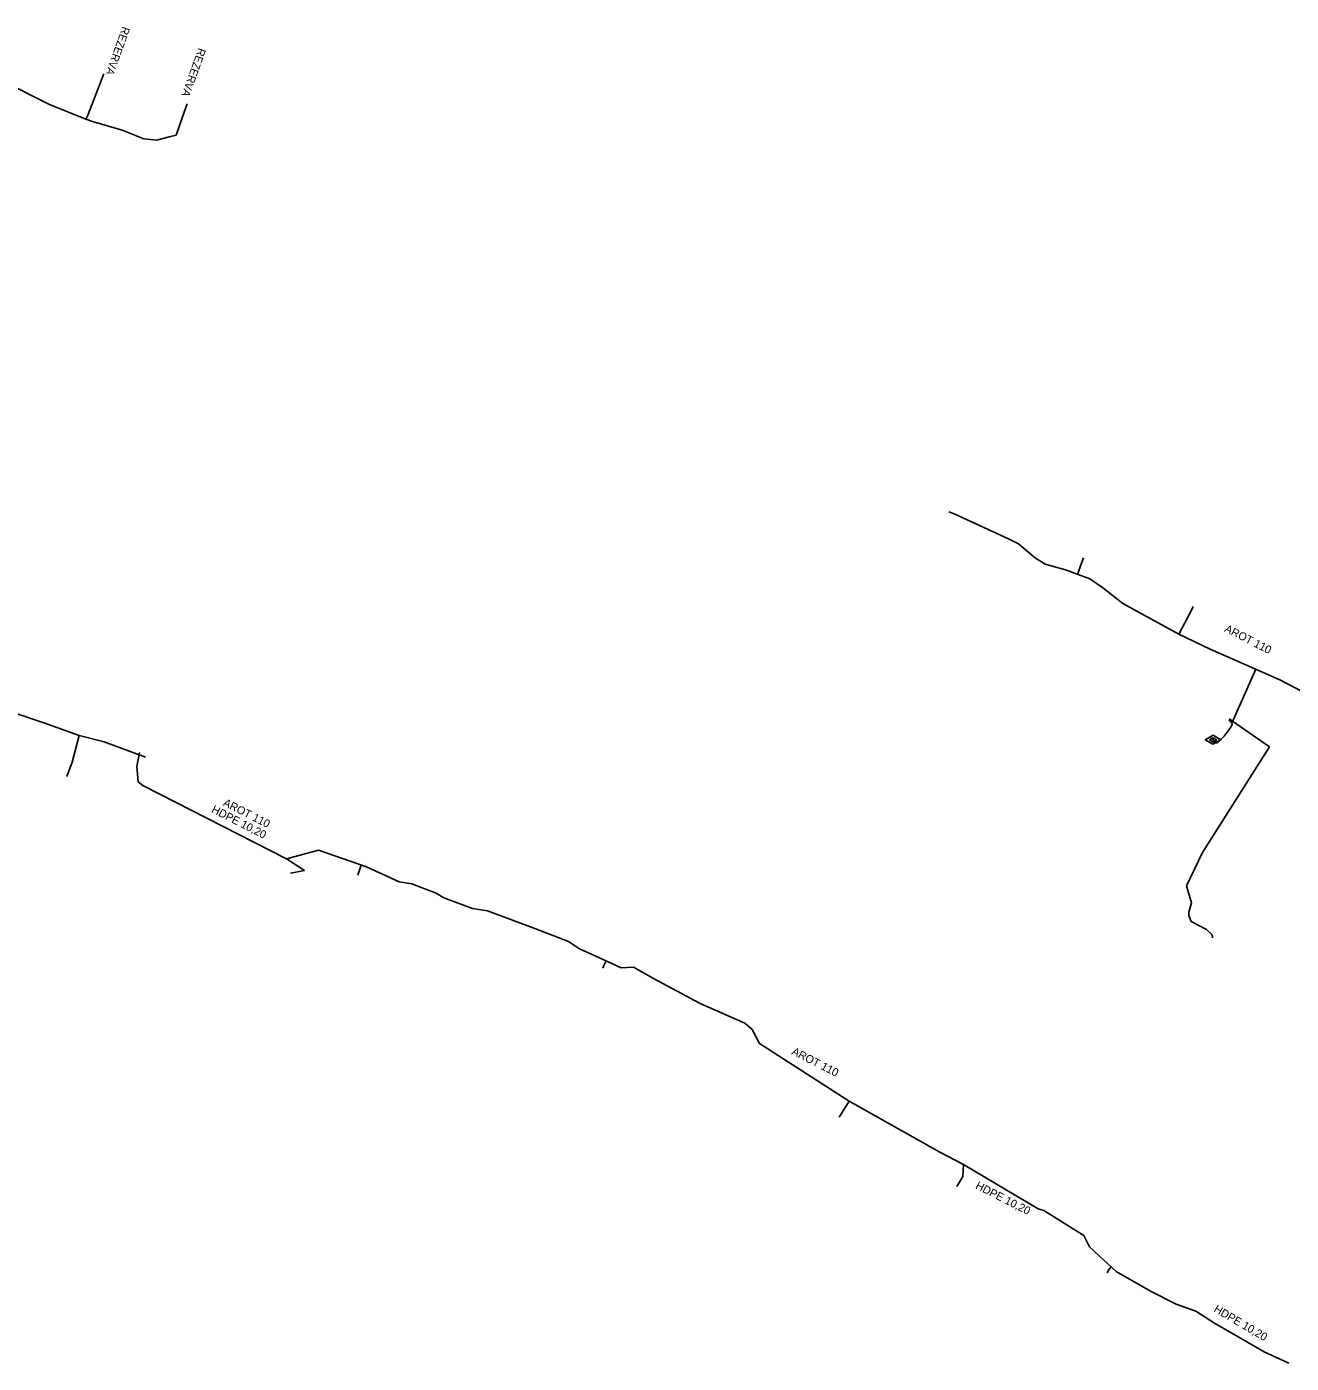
# Model space of a CAD drawing. Extents: x -651943 to -618711, y -1138561 to -1100552.
# Drawn here: x -644703.5 to -644585, y -1119211.8 to -1119086.6 of the extents above; entities that cross this region are included whole.
import ezdxf

# ---------------------------------------------------------------- set-up
doc = ezdxf.new("R2010")
doc.units = 0
doc.layers.add('KT trasa', color=7, linetype='Continuous')
doc.layers.add('KT zařízení', color=7, linetype='Continuous')

# ---------------------------------------------------------------- blocks, each defined once
blk = doc.blocks.new('TVSPO_1')
at = {"layer": 'KT zařízení'}
for p, q in [((-0.074, 0.002), (0, 0.044)), ((-0.001, -0.041), (-0.074, 0.002)), ((-0.035, 0), (0, 0.02)), ((0.073, 0.001), (-0.001, -0.041)), ((0, 0.044), (0.073, 0.001)), ((0, 0.02), (0.035, 0)), ((0.035, 0), (0, -0.02)), ((0, -0.02), (-0.035, 0))]:
    blk.add_line(p, q, dxfattribs=at)

msp = doc.modelspace()

# ---------------------------------------------------------------- linework, layer by layer
at = {"layer": 'KT trasa'}
for p, q in [((-644706.01, -1119091.49), (-644701.34, -1119093.83)), ((-644697.74, -1119094.84), (-644696.45, -1119091.53)), ((-644696.24, -1119090.96), (-644696.45, -1119091.53)), ((-644701.34, -1119093.83), (-644697.93, -1119095.23)), ((-644688.43, -1119093.77), (-644688.71, -1119094.56)), ((-644697.93, -1119095.23), (-644697.74, -1119094.84)), ((-644697.93, -1119095.23), (-644697.31, -1119095.42)), ((-644689.45, -1119096.73), (-644688.71, -1119094.56)), ((-644697.31, -1119095.42), (-644694.52, -1119096.26)), ((-644694.52, -1119096.26), (-644692.5, -1119097.07)), ((-644692.5, -1119097.07), (-644691.27, -1119097.17)), ((-644691.27, -1119097.17), (-644690.13, -1119096.87)), ((-644690.13, -1119096.87), (-644689.45, -1119096.73)), ((-644616.56, -1119132.22), (-644617.06, -1119132.01)), ((-644611.47, -1119134.54), (-644616.56, -1119132.22)), ((-644610.53, -1119135.01), (-644611.47, -1119134.54)), ((-644608.93, -1119136.35), (-644610.53, -1119135.01)), ((-644608.03, -1119136.93), (-644608.93, -1119136.35)), ((-644604.42, -1119136.34), (-644604.59, -1119136.75)), ((-644606.13, -1119137.47), (-644608.03, -1119136.93)), ((-644603.83, -1119138.3), (-644606.13, -1119137.47)), ((-644605, -1119137.88), (-644604.59, -1119136.75)), ((-644602.64, -1119139.1), (-644603.83, -1119138.3)), ((-644600.75, -1119140.61), (-644602.64, -1119139.1)), ((-644595.51, -1119143.47), (-644600.75, -1119140.61)), ((-644594.39, -1119141.36), (-644595.51, -1119143.47)), ((-644594.17, -1119140.88), (-644594.39, -1119141.36)), ((-644592.55, -1119144.89), (-644595.51, -1119143.47)), ((-644586.03, -1119147.77), (-644592.55, -1119144.89)), ((-644588.29, -1119146.77), (-644590.52, -1119151.82)), ((-644584.07, -1119148.79), (-644586.03, -1119147.77)), ((-644704.82, -1119150.8), (-644701.87, -1119151.79)), ((-644590.65, -1119151.64), (-644590.82, -1119151.55)), ((-644587.01, -1119154.06), (-644590.77, -1119151.42)), ((-644587.01, -1119154.06), (-644590.77, -1119151.42)), ((-644590.52, -1119151.82), (-644590.65, -1119151.64)), ((-644698.54, -1119152.99), (-644701.87, -1119151.79)), ((-644698.54, -1119152.99), (-644699.2, -1119155.49)), ((-644696.22, -1119153.57), (-644698.54, -1119152.99)), ((-644591.24, -1119153.03), (-644590.68, -1119152.31)), ((-644590.68, -1119152.31), (-644590.5, -1119151.96)), ((-644590.5, -1119151.96), (-644590.52, -1119151.82)), ((-644692.35, -1119155.02), (-644696.22, -1119153.57)), ((-644593.29, -1119163.96), (-644587.01, -1119154.06)), ((-644593.29, -1119163.96), (-644587.01, -1119154.06)), ((-644592.63, -1119153.11), (-644592.29, -1119153.4)), ((-644592.29, -1119153.4), (-644591.9, -1119153.7)), ((-644591.9, -1119153.7), (-644591.24, -1119153.03)), ((-644699.71, -1119156.83), (-644699.2, -1119155.49)), ((-644693.14, -1119155.88), (-644692.91, -1119154.58)), ((-644693.01, -1119157.32), (-644693.14, -1119155.88)), ((-644692.58, -1119157.66), (-644693.01, -1119157.32)), ((-644692.58, -1119157.66), (-644679.11, -1119164.53)), ((-644679.11, -1119164.53), (-644676.13, -1119163.74)), ((-644671.63, -1119165.29), (-644676.13, -1119163.74)), ((-644594.78, -1119167.08), (-644593.29, -1119163.96)), ((-644594.78, -1119167.08), (-644593.29, -1119163.96)), ((-644677.45, -1119165.62), (-644679.11, -1119164.53)), ((-644672.11, -1119165.12), (-644672.27, -1119165.59)), ((-644668.57, -1119166.69), (-644671.63, -1119165.29)), ((-644678.76, -1119165.88), (-644677.45, -1119165.62)), ((-644672.45, -1119166.08), (-644672.27, -1119165.59)), ((-644667.37, -1119166.9), (-644668.57, -1119166.69)), ((-644665.1, -1119167.77), (-644667.37, -1119166.9)), ((-644664.39, -1119168.2), (-644665.1, -1119167.77)), ((-644594.78, -1119167.08), (-644594.3, -1119168.68)), ((-644661.68, -1119169.19), (-644664.39, -1119168.2)), ((-644660.28, -1119169.43), (-644661.68, -1119169.19)), ((-644594.3, -1119168.68), (-644594.55, -1119169.53)), ((-644655.85, -1119171.08), (-644660.28, -1119169.43)), ((-644594.55, -1119169.53), (-644594.57, -1119169.85)), ((-644594.57, -1119169.85), (-644594.49, -1119170.02)), ((-644594.49, -1119170.02), (-644594.33, -1119170.42)), ((-644594.33, -1119170.42), (-644592.92, -1119171.15)), ((-644652.7, -1119172.29), (-644655.85, -1119171.08)), ((-644592.92, -1119171.15), (-644592.37, -1119171.67)), ((-644592.37, -1119171.67), (-644592.35, -1119171.96)), ((-644651.68, -1119172.99), (-644652.7, -1119172.29)), ((-644650.12, -1119173.68), (-644651.68, -1119172.99)), ((-644647.75, -1119174.75), (-644650.12, -1119173.68)), ((-644649.17, -1119174.11), (-644649.37, -1119174.55)), ((-644649.48, -1119174.8), (-644649.37, -1119174.55)), ((-644646.59, -1119174.71), (-644647.75, -1119174.75)), ((-644644.73, -1119175.76), (-644646.59, -1119174.71)), ((-644640.37, -1119178.1), (-644644.73, -1119175.76)), ((-644636.18, -1119179.95), (-644640.37, -1119178.1)), ((-644636.18, -1119179.95), (-644635.48, -1119180.53)), ((-644635.48, -1119180.53), (-644634.79, -1119181.86)), ((-644634.79, -1119181.86), (-644626.4, -1119187.24)), ((-644626.4, -1119187.24), (-644627.27, -1119188.66)), ((-644617.89, -1119192.05), (-644626.4, -1119187.24)), ((-644627.33, -1119188.74), (-644627.27, -1119188.66)), ((-644617.89, -1119192.05), (-644615.67, -1119193.19)), ((-644616.3, -1119195.25), (-644615.75, -1119194.31)), ((-644615.67, -1119193.19), (-644615.75, -1119194.31)), ((-644608.69, -1119197.33), (-644615.67, -1119193.19)), ((-644608.16, -1119197.5), (-644608.69, -1119197.33)), ((-644604.4, -1119199.84), (-644608.16, -1119197.5)), ((-644604.22, -1119200.22), (-644604.4, -1119199.84)), ((-644603.87, -1119200.92), (-644604.22, -1119200.22)), ((-644602.98, -1119201.74), (-644603.87, -1119200.92)), ((-644601.37, -1119203.21), (-644602.98, -1119201.74)), ((-644602.22, -1119203.33), (-644602.03, -1119203)), ((-644601.84, -1119202.79), (-644602.03, -1119203)), ((-644598.17, -1119205.06), (-644601.37, -1119203.21)), ((-644595.75, -1119206.28), (-644598.17, -1119205.06)), ((-644593.91, -1119206.93), (-644595.75, -1119206.28)), ((-644592.15, -1119208.05), (-644593.91, -1119206.93)), ((-644587.5, -1119210.74), (-644592.15, -1119208.05)), ((-644585.18, -1119211.82), (-644587.5, -1119210.74))]:
    msp.add_line(p, q, dxfattribs=at)

# ---------------------------------------------------------------- block references
at = {"layer": 'KT zařízení', "xscale": 10, "yscale": 10}
msp.add_blockref('TVSPO_1', (-644592.29, -1119153.4), dxfattribs=at)

# ---------------------------------------------------------------- texts
at = {"layer": 'KT zařízení'}
for s, rotation, p in [('REZERVA', 250.2011, (-644694.48, -1119086.48)), ('REZERVA', 250.2011, (-644687.36, -1119088.49)), ('AROT 110', 332.9926, (-644591.28, -1119143.21)), ('AROT 110', 332.9926, (-644685.13, -1119159.52)), ('HDPE 10,20', 332.9926, (-644686.22, -1119160.15)), ('AROT 110', 332.9926, (-644631.85, -1119182.83)), ('HDPE 10,20', 332.9926, (-644614.62, -1119195.41)), ('HDPE 10,20', 329.5335, (-644592.29, -1119206.94))]:
    msp.add_text(s, height=0.75, rotation=rotation, dxfattribs=at).set_placement(p)

doc.saveas('drawing.dxf')
